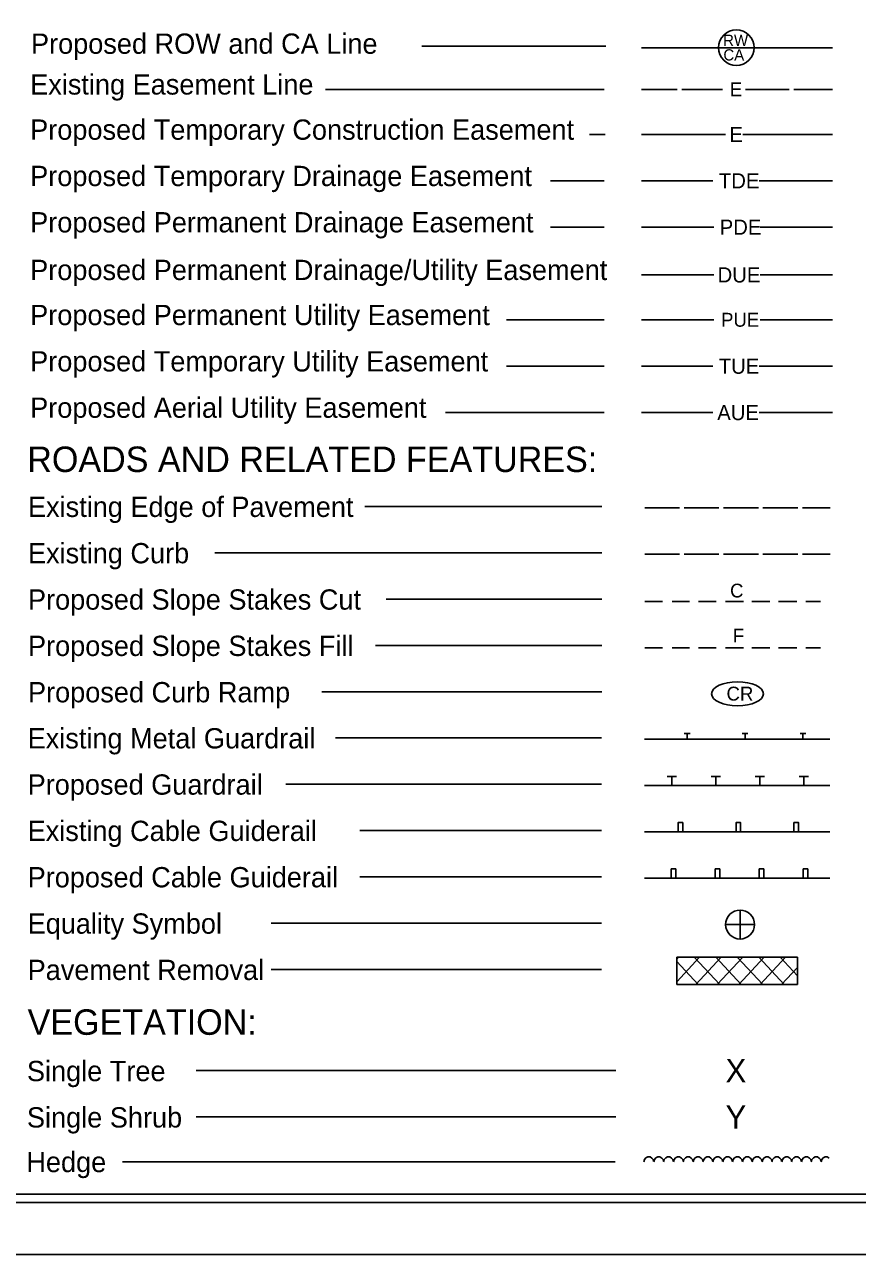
# Model space of a CAD drawing. Extents: x 147589369 to 147592737, y 91898723 to 91900923.
# Drawn here: x 147590495 to 147591214, y 91898723 to 91899785 of the extents above; entities that cross this region are included whole.
import ezdxf

# ---------------------------------------------------------------- set-up
doc = ezdxf.new("R2010")
doc.units = 0
for name, color, linetype in [('Prop Easement Permanent Drainage Utility', 7, 'Continuous'), ('Prop WCC CELL', 7, 'Continuous'), ('Sheet Cutting Line CELL', 7, 'Continuous'), ('Sheet Plot Border Inside CELL', 7, 'Continuous'), ('Sheet Plot Border Outside CELL', 7, 'Continuous'), ('Sheet Symbology CELL', 7, 'Continuous')]:
    doc.layers.add(name, color=color, linetype=linetype)

msp = doc.modelspace()

# ---------------------------------------------------------------- linework, layer by layer
at = {"layer": 'Prop Easement Permanent Drainage Utility'}
for p, q in [((147591027.1, 91899568.6), (147591089.7, 91899568.6)), ((147591129.7, 91899568.6), (147591192.1, 91899568.6))]:
    msp.add_line(p, q, dxfattribs=at)
at = {"layer": 'Prop WCC CELL'}
msp.add_ellipse((147591110.1, 91899207), major_axis=(22.4, 0), ratio=0.462467, dxfattribs=at)
at = {"layer": 'Sheet Cutting Line CELL'}
msp.add_line((147589369.3, 91898723.1), (147592737.3, 91898723.1), dxfattribs=at)
at = {"layer": 'Sheet Plot Border Inside CELL'}
msp.add_lwpolyline([(147589395.3, 91898768), (147592728.3, 91898768), (147592728.3, 91900878.2), (147589395.3, 91900878.2)], close=True, dxfattribs=at)
at = {"layer": 'Sheet Plot Border Outside CELL'}
msp.add_lwpolyline([(147589369.3, 91898723.1), (147592737.3, 91898723.1), (147592737.3, 91900923.1), (147589369.3, 91900923.1)], close=True, dxfattribs=at)
at = {"layer": 'Sheet Symbology CELL'}
for p, q in [((147590996.3, 91899765.9), (147590837.6, 91899765.9)), ((147591027.1, 91899764.4), (147591192.1, 91899764.4)), ((147590995, 91899728.7), (147590754.4, 91899728.7)), ((147591027.1, 91899728.7), (147591058.1, 91899728.7)), ((147591062.1, 91899728.7), (147591097.1, 91899728.7)), ((147591117.1, 91899728.7), (147591154.6, 91899728.7)), ((147591158.6, 91899728.7), (147591192.1, 91899728.7)), ((147590995.8, 91899689.8), (147590982.4, 91899689.8)), ((147591027.1, 91899689.8), (147591032.3, 91899689.8)), ((147591032.3, 91899689.8), (147591099.8, 91899689.8)), ((147591114.8, 91899689.8), (147591182.3, 91899689.8)), ((147591182.3, 91899689.8), (147591192.1, 91899689.8)), ((147590995, 91899649.8), (147590948.7, 91899649.8)), ((147591027.1, 91899649.8), (147591033.8, 91899649.8)), ((147591033.8, 91899649.8), (147591088.8, 91899649.8)), ((147591128.8, 91899649.8), (147591183.8, 91899649.8)), ((147591183.8, 91899649.8), (147591192.1, 91899649.8)), ((147590995, 91899609.8), (147590948.7, 91899609.8)), ((147591027.1, 91899609.8), (147591034.7, 91899609.8)), ((147591034.7, 91899609.8), (147591089.7, 91899609.8)), ((147591129.7, 91899609.8), (147591184.7, 91899609.8)), ((147591184.7, 91899609.8), (147591192.1, 91899609.8)), ((147590995, 91899529.8), (147590910.7, 91899529.8)), ((147591027.1, 91899529.8), (147591034.7, 91899529.8)), ((147591034.7, 91899529.8), (147591089.7, 91899529.8)), ((147591129.7, 91899529.8), (147591184.7, 91899529.8)), ((147591184.7, 91899529.8), (147591192.1, 91899529.8)), ((147590995, 91899489.8), (147590910.7, 91899489.8)), ((147591027.1, 91899489.8), (147591033.8, 91899489.8)), ((147591033.8, 91899489.8), (147591088.8, 91899489.8)), ((147591128.8, 91899489.8), (147591183.8, 91899489.8)), ((147591183.8, 91899489.8), (147591192.1, 91899489.8)), ((147590995, 91899449.8), (147590858.1, 91899449.8)), ((147591027.1, 91899449.8), (147591033.8, 91899449.8)), ((147591033.8, 91899449.8), (147591088.8, 91899449.8)), ((147591128.8, 91899449.8), (147591183.8, 91899449.8)), ((147591183.8, 91899449.8), (147591192.1, 91899449.8)), ((147590993.1, 91899368.7), (147590788.4, 91899368.7)), ((147591030.1, 91899367.6), (147591060.1, 91899367.6)), ((147591064.1, 91899367.6), (147591094.1, 91899367.6)), ((147591098.1, 91899367.6), (147591128.1, 91899367.6)), ((147591132.1, 91899367.6), (147591162.1, 91899367.6)), ((147591166.1, 91899367.6), (147591190.1, 91899367.6)), ((147590993.1, 91899328.7), (147590658.8, 91899328.7)), ((147591030.1, 91899327.6), (147591060.1, 91899327.6)), ((147591064.1, 91899327.6), (147591094.1, 91899327.6)), ((147591098.1, 91899327.6), (147591128.1, 91899327.6)), ((147591132.1, 91899327.6), (147591162.1, 91899327.6)), ((147591166.1, 91899327.6), (147591190.1, 91899327.6)), ((147590993.1, 91899288.7), (147590806.7, 91899288.7)), ((147591030.1, 91899286.6), (147591045.3, 91899286.6)), ((147591068.7, 91899286.6), (147591053.6, 91899286.6)), ((147591091.7, 91899286.6), (147591076.5, 91899286.6)), ((147591115.2, 91899286.6), (147591099.6, 91899286.6)), ((147591138.1, 91899286.6), (147591122.6, 91899286.6)), ((147591161.2, 91899286.6), (147591145.5, 91899286.6)), ((147591181.8, 91899286.6), (147591169, 91899286.6)), ((147590993.1, 91899248.7), (147590797.6, 91899248.7)), ((147591030.1, 91899246.6), (147591045.3, 91899246.6)), ((147591068.7, 91899246.6), (147591053.6, 91899246.6)), ((147591091.7, 91899246.6), (147591076.5, 91899246.6)), ((147591115.2, 91899246.6), (147591099.6, 91899246.6)), ((147591138.1, 91899246.6), (147591122.6, 91899246.6)), ((147591161.2, 91899246.6), (147591145.5, 91899246.6)), ((147591181.8, 91899246.6), (147591169, 91899246.6)), ((147590993.1, 91899208.7), (147590751.2, 91899208.7)), ((147591064.1, 91899172.8), (147591069.1, 91899172.8)), ((147591066.6, 91899167.8), (147591066.6, 91899172.8)), ((147591114.1, 91899172.8), (147591119.1, 91899172.8)), ((147591116.6, 91899167.8), (147591116.6, 91899172.8)), ((147591164.1, 91899172.8), (147591169.1, 91899172.8)), ((147591166.6, 91899167.8), (147591166.6, 91899172.8)), ((147590992.8, 91899168.9), (147590763.1, 91899168.9)), ((147591029.8, 91899167.8), (147591189.8, 91899167.8)), ((147590992.8, 91899128.9), (147590720.3, 91899128.9)), ((147591049.3, 91899135.7), (147591057.3, 91899135.7)), ((147591053.3, 91899127.8), (147591053.3, 91899135.7)), ((147591087.3, 91899135.7), (147591095.3, 91899135.7)), ((147591091.3, 91899127.8), (147591091.3, 91899135.7)), ((147591125.3, 91899135.7), (147591133.3, 91899135.7)), ((147591129.3, 91899127.8), (147591129.3, 91899135.7)), ((147591163.3, 91899135.7), (147591171.3, 91899135.7)), ((147591167.3, 91899127.8), (147591167.3, 91899135.7)), ((147591189.8, 91899127.8), (147591029.8, 91899127.8)), ((147590992.8, 91899088.9), (147590784.2, 91899088.9)), ((147591029.8, 91899087.8), (147591189.8, 91899087.8)), ((147590992.8, 91899048.9), (147590784.2, 91899048.9)), ((147591029.8, 91899047.8), (147591189.8, 91899047.8)), ((147591112.3, 91899020.3), (147591112.3, 91899007.8)), ((147590992.8, 91899008.9), (147590707.5, 91899008.9)), ((147591099.8, 91899007.8), (147591112.3, 91899007.8)), ((147591112.3, 91899007.8), (147591112.3, 91898995.3)), ((147591112.3, 91899007.8), (147591124.8, 91899007.8)), ((147591057.7, 91898979.5), (147591161.9, 91898979.5)), ((147591057.7, 91898956.1), (147591057.7, 91898979.5)), ((147591057.7, 91898978.3), (147591058.8, 91898979.5)), ((147591057.7, 91898958.4), (147591077.4, 91898979.5)), ((147591076.2, 91898956.1), (147591057.7, 91898975.9)), ((147591094.8, 91898956.1), (147591072.8, 91898979.5)), ((147591074, 91898956.1), (147591096, 91898979.5)), ((147591113.3, 91898956.1), (147591091.4, 91898979.5)), ((147591092.5, 91898956.1), (147591114.6, 91898979.5)), ((147591131.9, 91898956.1), (147591109.9, 91898979.5)), ((147591111.1, 91898956.1), (147591133.1, 91898979.5)), ((147591150.5, 91898956.1), (147591128.4, 91898979.5)), ((147591129.7, 91898956.1), (147591151.6, 91898979.5)), ((147591161.9, 91898963.6), (147591147, 91898979.5)), ((147591148.2, 91898956.1), (147591161.9, 91898970.7)), ((147591161.9, 91898979.5), (147591161.9, 91898956.1)), ((147590992.8, 91898968.9), (147590707.5, 91898968.9)), ((147591161.9, 91898956.1), (147591057.7, 91898956.1)), ((147591005, 91898881.7), (147590642.8, 91898881.7)), ((147591005, 91898841.7), (147590642.8, 91898841.7)), ((147591004.5, 91898803.1), (147590579.1, 91898803.1)), ((147591029.3, 91898803.1), (147591029.9, 91898805)), ((147591029.9, 91898805), (147591031.1, 91898806.3)), ((147591031.1, 91898806.3), (147591032.7, 91898807.2)), ((147591032.7, 91898807.2), (147591034.6, 91898807.2)), ((147591034.6, 91898807.2), (147591036.2, 91898806.2)), ((147591036.2, 91898806.2), (147591037.3, 91898804.9)), ((147591037.3, 91898804.9), (147591037.7, 91898803.2)), ((147591037.8, 91898803.1), (147591038.4, 91898805)), ((147591038.4, 91898805), (147591039.6, 91898806.3)), ((147591039.6, 91898806.3), (147591041.2, 91898807.2)), ((147591041.2, 91898807.2), (147591043.1, 91898807.2)), ((147591043.1, 91898807.2), (147591044.7, 91898806.2)), ((147591044.7, 91898806.2), (147591045.8, 91898804.9)), ((147591045.8, 91898804.9), (147591046.2, 91898803.2)), ((147591046.3, 91898803.1), (147591046.9, 91898805)), ((147591046.9, 91898805), (147591048.1, 91898806.3)), ((147591048.1, 91898806.3), (147591049.7, 91898807.2)), ((147591049.7, 91898807.2), (147591051.6, 91898807.2)), ((147591051.6, 91898807.2), (147591053.2, 91898806.2)), ((147591053.2, 91898806.2), (147591054.3, 91898804.9)), ((147591054.3, 91898804.9), (147591054.7, 91898803.2)), ((147591054.8, 91898803.1), (147591055.4, 91898805)), ((147591055.4, 91898805), (147591056.6, 91898806.3)), ((147591056.6, 91898806.3), (147591058.2, 91898807.2)), ((147591058.2, 91898807.2), (147591060.1, 91898807.2)), ((147591060.1, 91898807.2), (147591061.7, 91898806.2)), ((147591061.7, 91898806.2), (147591062.8, 91898804.9)), ((147591062.8, 91898804.9), (147591063.2, 91898803.2)), ((147591063.3, 91898803.1), (147591063.9, 91898805)), ((147591063.9, 91898805), (147591065.1, 91898806.3)), ((147591065.1, 91898806.3), (147591066.7, 91898807.2)), ((147591066.7, 91898807.2), (147591068.6, 91898807.2)), ((147591068.6, 91898807.2), (147591070.2, 91898806.2)), ((147591070.2, 91898806.2), (147591071.3, 91898804.9)), ((147591071.3, 91898804.9), (147591071.7, 91898803.2)), ((147591071.8, 91898803.1), (147591072.4, 91898805)), ((147591072.4, 91898805), (147591073.6, 91898806.3)), ((147591073.6, 91898806.3), (147591075.2, 91898807.2)), ((147591075.2, 91898807.2), (147591077.1, 91898807.2)), ((147591077.1, 91898807.2), (147591078.7, 91898806.2)), ((147591078.7, 91898806.2), (147591079.8, 91898804.9)), ((147591079.8, 91898804.9), (147591080.2, 91898803.2)), ((147591080.3, 91898803.1), (147591080.9, 91898805)), ((147591080.9, 91898805), (147591082.1, 91898806.3)), ((147591082.1, 91898806.3), (147591083.7, 91898807.2)), ((147591083.7, 91898807.2), (147591085.6, 91898807.2)), ((147591085.6, 91898807.2), (147591087.2, 91898806.2)), ((147591087.2, 91898806.2), (147591088.3, 91898804.9)), ((147591088.3, 91898804.9), (147591088.7, 91898803.2)), ((147591088.8, 91898803.1), (147591089.4, 91898805)), ((147591089.4, 91898805), (147591090.6, 91898806.3)), ((147591090.6, 91898806.3), (147591092.2, 91898807.2)), ((147591092.2, 91898807.2), (147591094.1, 91898807.2)), ((147591094.1, 91898807.2), (147591095.7, 91898806.2)), ((147591095.7, 91898806.2), (147591096.8, 91898804.9)), ((147591096.8, 91898804.9), (147591097.2, 91898803.2)), ((147591097.3, 91898803.1), (147591097.9, 91898805)), ((147591097.9, 91898805), (147591099.1, 91898806.3)), ((147591099.1, 91898806.3), (147591100.7, 91898807.2)), ((147591100.7, 91898807.2), (147591102.6, 91898807.2)), ((147591102.6, 91898807.2), (147591104.2, 91898806.2)), ((147591104.2, 91898806.2), (147591105.3, 91898804.9)), ((147591105.3, 91898804.9), (147591105.7, 91898803.2)), ((147591105.8, 91898803.1), (147591106.4, 91898805)), ((147591106.4, 91898805), (147591107.6, 91898806.3)), ((147591107.6, 91898806.3), (147591109.2, 91898807.2)), ((147591109.2, 91898807.2), (147591111.1, 91898807.2)), ((147591111.1, 91898807.2), (147591112.7, 91898806.2)), ((147591112.7, 91898806.2), (147591113.8, 91898804.9)), ((147591113.8, 91898804.9), (147591114.2, 91898803.2)), ((147591114.3, 91898803.1), (147591114.9, 91898805)), ((147591114.9, 91898805), (147591116.1, 91898806.3)), ((147591116.1, 91898806.3), (147591117.7, 91898807.2)), ((147591117.7, 91898807.2), (147591119.6, 91898807.2)), ((147591119.6, 91898807.2), (147591121.2, 91898806.2)), ((147591121.2, 91898806.2), (147591122.3, 91898804.9)), ((147591122.3, 91898804.9), (147591122.7, 91898803.2)), ((147591122.8, 91898803.1), (147591123.4, 91898805)), ((147591123.4, 91898805), (147591124.6, 91898806.3)), ((147591124.6, 91898806.3), (147591126.2, 91898807.2)), ((147591126.2, 91898807.2), (147591128.1, 91898807.2)), ((147591128.1, 91898807.2), (147591129.7, 91898806.2)), ((147591129.7, 91898806.2), (147591130.8, 91898804.9)), ((147591130.8, 91898804.9), (147591131.2, 91898803.2)), ((147591131.3, 91898803.1), (147591131.9, 91898805)), ((147591131.9, 91898805), (147591133.1, 91898806.3)), ((147591133.1, 91898806.3), (147591134.7, 91898807.2)), ((147591134.7, 91898807.2), (147591136.6, 91898807.2)), ((147591136.6, 91898807.2), (147591138.2, 91898806.2)), ((147591138.2, 91898806.2), (147591139.3, 91898804.9)), ((147591139.3, 91898804.9), (147591139.7, 91898803.2)), ((147591139.8, 91898803.1), (147591140.4, 91898805)), ((147591140.4, 91898805), (147591141.6, 91898806.3)), ((147591141.6, 91898806.3), (147591143.2, 91898807.2)), ((147591143.2, 91898807.2), (147591145.1, 91898807.2)), ((147591145.1, 91898807.2), (147591146.7, 91898806.2)), ((147591146.7, 91898806.2), (147591147.8, 91898804.9)), ((147591147.8, 91898804.9), (147591148.2, 91898803.2)), ((147591148.3, 91898803.1), (147591148.9, 91898805)), ((147591148.9, 91898805), (147591150.1, 91898806.3)), ((147591150.1, 91898806.3), (147591151.7, 91898807.2)), ((147591151.7, 91898807.2), (147591153.6, 91898807.2)), ((147591153.6, 91898807.2), (147591155.2, 91898806.2)), ((147591155.2, 91898806.2), (147591156.3, 91898804.9)), ((147591156.3, 91898804.9), (147591156.7, 91898803.2)), ((147591156.8, 91898803.1), (147591157.4, 91898805)), ((147591157.4, 91898805), (147591158.6, 91898806.3)), ((147591158.6, 91898806.3), (147591160.2, 91898807.2)), ((147591160.2, 91898807.2), (147591162.1, 91898807.2)), ((147591162.1, 91898807.2), (147591163.7, 91898806.2)), ((147591163.7, 91898806.2), (147591164.8, 91898804.9)), ((147591164.8, 91898804.9), (147591165.2, 91898803.2)), ((147591165.3, 91898803.1), (147591165.9, 91898805)), ((147591165.9, 91898805), (147591167.1, 91898806.3)), ((147591167.1, 91898806.3), (147591168.7, 91898807.2)), ((147591168.7, 91898807.2), (147591170.6, 91898807.2)), ((147591170.6, 91898807.2), (147591172.2, 91898806.2)), ((147591172.2, 91898806.2), (147591173.3, 91898804.9)), ((147591173.3, 91898804.9), (147591173.7, 91898803.2)), ((147591173.8, 91898803.1), (147591174.4, 91898805)), ((147591174.4, 91898805), (147591175.6, 91898806.3)), ((147591175.6, 91898806.3), (147591177.2, 91898807.2)), ((147591177.2, 91898807.2), (147591179.1, 91898807.2)), ((147591179.1, 91898807.2), (147591180.7, 91898806.2)), ((147591180.7, 91898806.2), (147591181.8, 91898804.9)), ((147591181.8, 91898804.9), (147591182.2, 91898803.2)), ((147591182.3, 91898803.1), (147591182.9, 91898805)), ((147591182.9, 91898805), (147591184.1, 91898806.3)), ((147591184.1, 91898806.3), (147591185.7, 91898807.2)), ((147591185.7, 91898807.2), (147591187.6, 91898807.2)), ((147591187.6, 91898807.2), (147591189.2, 91898806.2)), ((147591189.2, 91898806.2), (147591189.3, 91898806.1))]:
    msp.add_line(p, q, dxfattribs=at)
for points in [[(147592703.3, 91900873.1), (147589703.3, 91900873.1), (147589703.3, 91898775.1), (147592703.3, 91898775.1)], [(147591058.8, 91899087.8), (147591062.8, 91899087.8), (147591062.8, 91899095.8), (147591058.8, 91899095.8)], [(147591108.8, 91899087.8), (147591112.8, 91899087.8), (147591112.8, 91899095.8), (147591108.8, 91899095.8)], [(147591158.8, 91899087.8), (147591162.8, 91899087.8), (147591162.8, 91899095.8), (147591158.8, 91899095.8)], [(147591052.8, 91899055.8), (147591056.8, 91899055.8), (147591056.8, 91899047.8), (147591052.8, 91899047.8)], [(147591090.8, 91899055.8), (147591094.8, 91899055.8), (147591094.8, 91899047.8), (147591090.8, 91899047.8)], [(147591128.8, 91899055.8), (147591132.8, 91899055.8), (147591132.8, 91899047.8), (147591128.8, 91899047.8)], [(147591166.8, 91899055.8), (147591170.8, 91899055.8), (147591170.8, 91899047.8), (147591166.8, 91899047.8)]]:
    msp.add_lwpolyline(points, close=True, dxfattribs=at)
msp.add_circle((147591109.1, 91899764.7), 15.4, dxfattribs=at)
for start, end in [(89.9944, 179.9989), (359.9944, 89.9989), (179.9944, 269.9989), (269.9944, 359.9989)]:
    msp.add_arc((147591112.3, 91899007.8), 12.5, start, end, dxfattribs=at)

# ---------------------------------------------------------------- texts
at = {"layer": 'Prop Easement Permanent Drainage Utility'}
msp.add_text('DUE', height=13.1, dxfattribs=at).set_placement((147591092.9, 91899562))
at = {"layer": 'Prop WCC CELL'}
msp.add_text('CR', height=12, dxfattribs=at).set_placement((147591100.6, 91899201.1))
at = {"layer": 'Sheet Symbology CELL'}
for s, height, p in [('Proposed ROW and CA Line', 17.5, (147590500.2, 91899759.4)), ('RW', 9.68, (147591097.7, 91899766.2)), ('CA', 9.68, (147591097.9, 91899753.6)), ('Existing Easement Line', 17.5, (147590499.5, 91899724.2)), ('E', 12, (147591103.5, 91899722.7)), ('Proposed Temporary Construction Easement', 17.5, (147590499.5, 91899685.2)), ('E', 13.1, (147591103, 91899683.2)), ('Proposed Temporary Drainage Easement', 17.5, (147590499.5, 91899645.2)), ('TDE', 13.1, (147591094, 91899643.2)), ('Proposed Permanent Drainage Easement', 17.5, (147590499.5, 91899605.2)), ('PDE', 13.1, (147591094.7, 91899603.2)), ('Proposed Permanent Drainage/Utility Easement', 17.5, (147590499.5, 91899564.1)), ('Proposed Permanent Utility Easement', 17.5, (147590499.5, 91899525.2)), ('PUE', 12, (147591095.9, 91899523.8)), ('Proposed Temporary Utility Easement', 17.5, (147590499.5, 91899485.2)), ('TUE', 13.1, (147591093.9, 91899483.2)), ('Proposed Aerial Utility Easement', 17.5, (147590499.5, 91899445.2)), ('AUE', 13.1, (147591092.6, 91899443.2)), ('ROADS AND RELATED FEATURES:', 22, (147590497, 91899398.4)), ('Existing Edge of Pavement', 17.5, (147590497.6, 91899359.6)), ('Existing Curb', 17.5, (147590497.6, 91899319.6)), ('C', 11.9, (147591103.7, 91899290.1)), ('Proposed Slope Stakes Cut', 17.5, (147590497.6, 91899279.6)), ('Proposed Slope Stakes Fill', 17.5, (147590497.6, 91899239.6)), ('F', 11.9, (147591106.1, 91899251.3)), ('Proposed Curb Ramp', 17.5, (147590497.6, 91899199.6)), ('Existing Metal Guardrail', 17.5, (147590497.3, 91899159.8)), ('Proposed Guardrail', 17.5, (147590497.3, 91899119.9)), ('Existing Cable Guiderail', 17.5, (147590497.3, 91899079.9)), ('Proposed Cable Guiderail', 17.5, (147590497.3, 91899039.9)), ('Equality Symbol', 17.5, (147590497.3, 91898999.9)), ('Pavement Removal', 17.5, (147590497.3, 91898959.9)), ('VEGETATION:', 22, (147590497.3, 91898912.6)), ('Single Tree', 17.5, (147590496.7, 91898872.6)), ('X', 20, (147591099.8, 91898871.7)), ('Single Shrub', 17.5, (147590496.7, 91898832.6)), ('Y', 20, (147591099.8, 91898831.7)), ('Hedge', 17.5, (147590496.2, 91898794.1))]:
    msp.add_text(s, height=height, dxfattribs=at).set_placement(p)

doc.saveas('drawing.dxf')
